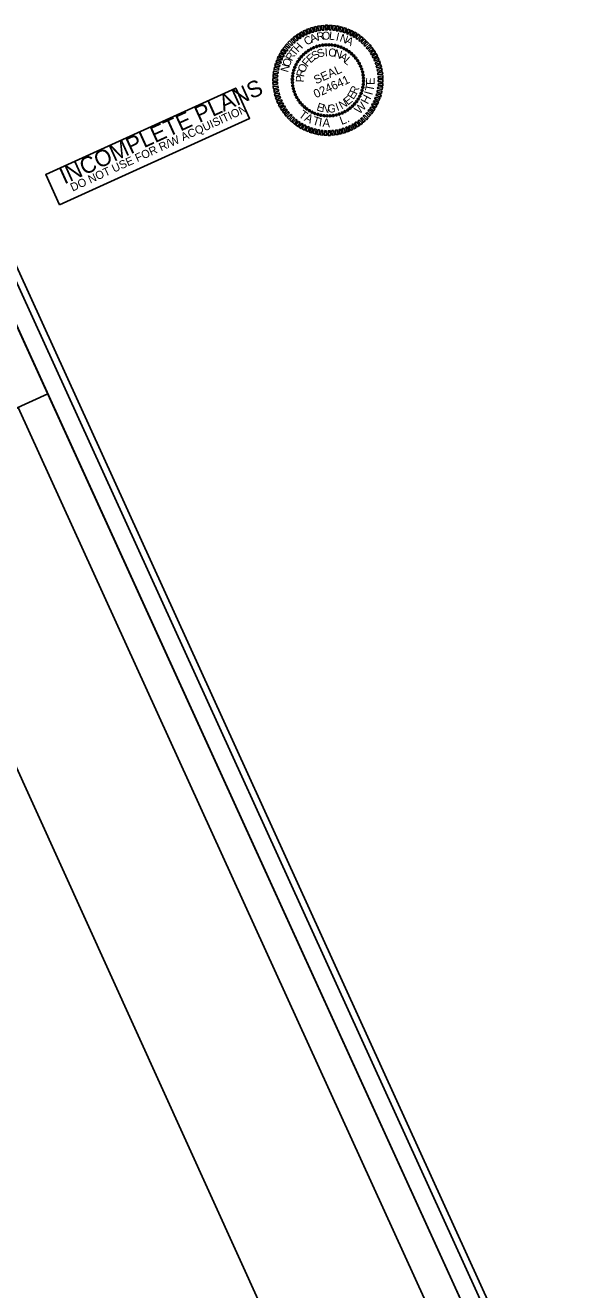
# Model space of a CAD drawing. Extents: x 2247910 to 2249896, y 662531 to 664266.
# Drawn here: x 2249507 to 2249896, y 663375 to 664266 of the extents above; entities that cross this region are included whole.
import ezdxf

# ---------------------------------------------------------------- set-up
doc = ezdxf.new("R2010")
doc.units = 0
for name, color, linetype in [('Sheet Clip Boundary CELL', 7, 'Continuous'), ('Sheet Layout Plan Border', 7, 'Continuous'), ('Sheet Plan CELL', 7, 'Continuous'), ('Sheet Plan Layout CELL', 7, 'Continuous'), ('Sheet Plot Border Inside CELL', 7, 'Continuous'), ('Sheet Plot Border Outside CELL', 7, 'Continuous'), ('Sheet Professional Seal CELL', 7, 'Continuous'), ('Sheet Sticker Incomplete CELL', 7, 'Continuous')]:
    doc.layers.add(name, color=color, linetype=linetype)

msp = doc.modelspace()

# ---------------------------------------------------------------- linework, layer by layer
at = {"layer": 'Sheet Clip Boundary CELL'}
msp.add_lwpolyline([(2248241.67, 663371.06), (2248489.82, 662824.78), (2248551.22, 662641.58), (2248585.88, 662667.26), (2249638.09, 663136.85), (2249825.2, 663222.11), (2249759.42, 663344.83), (2249697.59, 663317.15), (2249673.42, 663362.44), (2249425.27, 663908.72), (2249477.5, 663985.14), (2249333.25, 663919.41), (2249245.56, 664111.86), (2248806.18, 663911.31), (2248826.45, 663856.95), (2248820.45, 663848.41), (2248540.82, 663728.18), (2248517.28, 663777.91), (2248115.83, 663597.06)], close=True, dxfattribs=at)
at = {"layer": 'Sheet Layout Plan Border'}
msp.add_lwpolyline([(2248198.13, 663481.51), (2248575.77, 662652.77), (2249849.75, 663233.3), (2249502.05, 663996.33), (2249329.83, 663917.85), (2249242.13, 664110.3), (2248140.38, 663608.25)], close=True, dxfattribs=at)
at = {"layer": 'Sheet Plan CELL'}
for points in [[(2249435.32, 664198.33), (2248070.33, 663576.33), (2248505.72, 662620.85), (2249870.7, 663242.85)], [(2248505.72, 662620.85), (2248070.31, 663576.29), (2249253.26, 664115.38), (2249268.84, 664081.19), (2249359.88, 664122.68), (2249406.53, 664020.29), (2249497.53, 664061.77), (2249870.7, 663242.85)]]:
    msp.add_lwpolyline(points, close=True, dxfattribs=at)
at = {"layer": 'Sheet Plan Layout CELL'}
for points in [[(2249305.27, 663906.66), (2249523.01, 664005.88), (2249435.34, 664198.34), (2249217.58, 664099.11)], [(2248070.31, 663576.29), (2248505.72, 662620.85), (2249870.68, 663242.84), (2249522.99, 664005.87), (2249305.27, 663906.66), (2249217.58, 664099.11)]]:
    msp.add_lwpolyline(points, close=True, dxfattribs=at)
at = {"layer": 'Sheet Plot Border Inside CELL'}
msp.add_lwpolyline([(2248367.09, 662554.92), (2249883.1, 663245.75), (2249445.65, 664205.77), (2247929.62, 663514.94)], close=True, dxfattribs=at)
at = {"layer": 'Sheet Plot Border Outside CELL'}
msp.add_lwpolyline([(2248363.56, 662531.33), (2249895.5, 663229.41), (2249441.45, 664225.83), (2247909.5, 663527.75)], close=True, dxfattribs=at)
at = {"layer": 'Sheet Professional Seal CELL'}
for p, q in [((2249701.49, 664243.45), (2249701.49, 664243.45)), ((2249702.98, 664245), (2249702.98, 664245)), ((2249704.64, 664246.42), (2249704.64, 664246.42)), ((2249706.47, 664247.7), (2249706.47, 664247.7)), ((2249708.31, 664248.86), (2249708.31, 664248.86)), ((2249710.29, 664249.82), (2249710.29, 664249.82)), ((2249712.35, 664250.6), (2249712.35, 664250.6)), ((2249714.45, 664251.17), (2249714.45, 664251.17)), ((2249716.55, 664251.63), (2249716.55, 664251.63)), ((2249718.75, 664251.87), (2249718.75, 664251.87)), ((2249720.94, 664251.88), (2249720.94, 664251.88)), ((2249723.13, 664251.78), (2249723.13, 664251.78)), ((2249725.29, 664251.39), (2249725.29, 664251.39)), ((2249727.44, 664250.88), (2249727.44, 664250.88)), ((2249729.47, 664250.16), (2249729.47, 664250.16)), ((2249731.52, 664249.28), (2249731.52, 664249.28)), ((2249733.39, 664248.21), (2249733.39, 664248.21)), ((2249735.22, 664246.96), (2249735.22, 664246.96)), ((2249736.94, 664245.6), (2249736.94, 664245.6)), ((2249738.5, 664244.11), (2249738.5, 664244.11)), ((2249696.92, 664235.98), (2249696.92, 664235.98)), ((2249697.8, 664238.03), (2249697.8, 664238.03)), ((2249698.88, 664239.89), (2249698.88, 664239.89)), ((2249700.13, 664241.73), (2249700.13, 664241.73)), ((2249739.92, 664242.45), (2249739.92, 664242.45)), ((2249741.19, 664240.61), (2249741.19, 664240.61)), ((2249742.36, 664238.78), (2249742.36, 664238.78)), ((2249743.31, 664236.8), (2249743.31, 664236.8)), ((2249744.09, 664234.74), (2249744.09, 664234.74)), ((2249695.21, 664227.45), (2249695.21, 664227.45)), ((2249695.22, 664225.26), (2249695.22, 664225.26)), ((2249695.31, 664229.64), (2249695.31, 664229.64)), ((2249695.7, 664231.79), (2249695.7, 664231.79)), ((2249696.2, 664233.95), (2249696.2, 664233.95)), ((2249720.29, 664226.8), (2249720.29, 664226.8)), ((2249744.66, 664232.63), (2249744.66, 664232.63)), ((2249745.13, 664230.54), (2249745.13, 664230.54)), ((2249745.36, 664228.34), (2249745.36, 664228.34)), ((2249745.37, 664226.14), (2249745.37, 664226.14)), ((2249695.45, 664223.05), (2249695.45, 664223.05)), ((2249695.92, 664220.96), (2249695.92, 664220.96)), ((2249696.49, 664218.86), (2249696.49, 664218.86)), ((2249697.27, 664216.79), (2249697.27, 664216.79)), ((2249743.66, 664217.61), (2249743.66, 664217.61)), ((2249744.38, 664219.64), (2249744.38, 664219.64)), ((2249744.88, 664221.8), (2249744.88, 664221.8)), ((2249745.27, 664223.95), (2249745.27, 664223.95)), ((2249698.22, 664214.81), (2249698.22, 664214.81)), ((2249699.39, 664212.98), (2249699.39, 664212.98)), ((2249700.67, 664211.14), (2249700.67, 664211.14)), ((2249702.08, 664209.48), (2249702.08, 664209.48)), ((2249703.64, 664207.99), (2249703.64, 664207.99)), ((2249737.6, 664208.59), (2249737.6, 664208.59)), ((2249739.09, 664210.15), (2249739.09, 664210.15)), ((2249740.45, 664211.86), (2249740.45, 664211.86)), ((2249741.7, 664213.7), (2249741.7, 664213.7)), ((2249742.78, 664215.56), (2249742.78, 664215.56)), ((2249705.36, 664206.63), (2249705.36, 664206.63)), ((2249707.19, 664205.38), (2249707.19, 664205.38)), ((2249709.06, 664204.31), (2249709.06, 664204.31)), ((2249711.11, 664203.43), (2249711.11, 664203.43)), ((2249713.14, 664202.71), (2249713.14, 664202.71)), ((2249715.29, 664202.21), (2249715.29, 664202.21)), ((2249717.45, 664201.81), (2249717.45, 664201.81)), ((2249719.64, 664201.71), (2249719.64, 664201.71)), ((2249721.83, 664201.72), (2249721.83, 664201.72)), ((2249724.03, 664201.96), (2249724.03, 664201.96)), ((2249726.13, 664202.42), (2249726.13, 664202.42)), ((2249728.23, 664202.99), (2249728.23, 664202.99)), ((2249730.29, 664203.77), (2249730.29, 664203.77)), ((2249732.28, 664204.73), (2249732.28, 664204.73)), ((2249734.11, 664205.89), (2249734.11, 664205.89)), ((2249735.94, 664207.17), (2249735.94, 664207.17))]:
    msp.add_line(p, q, dxfattribs=at)
for points in [[(2249702.28, 664257.38), (2249700.45, 664260.06), (2249701.91, 664260.95), (2249703.31, 664258.01)], [(2249704.45, 664258.64), (2249702.87, 664261.5), (2249704.4, 664262.14), (2249705.56, 664259.1)], [(2249706.65, 664259.59), (2249705.31, 664262.55), (2249706.83, 664263.19), (2249707.77, 664260.05)], [(2249708.99, 664260.49), (2249707.82, 664263.53), (2249709.45, 664263.95), (2249710.17, 664260.81)], [(2249711.34, 664261.13), (2249710.42, 664264.22), (2249712.03, 664264.68), (2249712.49, 664261.49)], [(2249713.89, 664261.68), (2249713, 664264.85), (2249714.71, 664265.19), (2249714.95, 664261.89)], [(2249716.34, 664262.09), (2249715.74, 664265.22), (2249717.36, 664265.41), (2249717.44, 664262.21)], [(2249718.76, 664262.2), (2249718.5, 664265.55), (2249720.02, 664265.58), (2249719.95, 664262.36)], [(2249721.2, 664262.27), (2249721.12, 664265.47), (2249722.82, 664265.48), (2249722.43, 664262.23)], [(2249723.77, 664262.18), (2249723.82, 664265.33), (2249725.54, 664265.18), (2249724.89, 664262.03)], [(2249726.11, 664261.76), (2249726.5, 664265.13), (2249728.12, 664264.71), (2249727.36, 664261.67)], [(2249728.6, 664261.25), (2249729.14, 664264.52), (2249730.78, 664264.05), (2249729.75, 664261)], [(2249730.97, 664260.62), (2249731.75, 664263.84), (2249733.34, 664263.25), (2249732.14, 664260.34)], [(2249733.33, 664259.78), (2249734.31, 664262.81), (2249735.9, 664262.21), (2249734.35, 664259.36)], [(2249735.67, 664258.87), (2249736.83, 664261.87), (2249738.35, 664261.08), (2249736.72, 664258.25)], [(2249692.89, 664249.41), (2249690.27, 664251.3), (2249691.39, 664252.58), (2249693.7, 664250.28)], [(2249694.45, 664251.28), (2249692.07, 664253.38), (2249693.18, 664254.55), (2249695.47, 664252.07)], [(2249696.35, 664253.03), (2249694.06, 664255.28), (2249695.28, 664256.33), (2249697.16, 664253.78)], [(2249698.26, 664254.61), (2249696, 664257.04), (2249697.4, 664258.07), (2249699.12, 664255.28)], [(2249700.22, 664256.11), (2249698.16, 664258.69), (2249699.6, 664259.51), (2249701.25, 664256.74)], [(2249737.84, 664257.71), (2249739.2, 664260.64), (2249740.67, 664259.72), (2249738.78, 664257.1)], [(2249739.88, 664256.39), (2249741.5, 664259.22), (2249742.99, 664258.25), (2249740.93, 664255.77)], [(2249741.97, 664254.93), (2249743.79, 664257.68), (2249745.03, 664256.54), (2249742.91, 664254.31)], [(2249743.78, 664253.39), (2249745.84, 664255.97), (2249747.09, 664254.79), (2249744.69, 664252.59)], [(2249745.57, 664251.62), (2249747.8, 664254.07), (2249748.95, 664252.89), (2249746.46, 664250.87)], [(2249747.29, 664249.77), (2249749.73, 664252.14), (2249750.68, 664250.77), (2249748.05, 664248.96)], [(2249687.66, 664240.99), (2249684.75, 664242.08), (2249685.34, 664243.67), (2249688.24, 664242.02)], [(2249688.84, 664243.23), (2249685.89, 664244.52), (2249686.68, 664246.03), (2249689.43, 664244.21)], [(2249689.94, 664245.38), (2249687.2, 664246.93), (2249687.99, 664248.34), (2249690.7, 664246.38)], [(2249691.43, 664247.43), (2249688.62, 664249.12), (2249689.7, 664250.49), (2249692.04, 664248.37)], [(2249748.83, 664247.83), (2249751.31, 664250.01), (2249752.28, 664248.58), (2249749.54, 664247)], [(2249750.24, 664245.84), (2249752.91, 664247.82), (2249753.75, 664246.34), (2249750.92, 664244.83)], [(2249751.51, 664243.78), (2249754.3, 664245.49), (2249755.1, 664243.98), (2249752.1, 664242.73)], [(2249685.51, 664233.9), (2249682.34, 664234.33), (2249682.61, 664236.04), (2249685.7, 664235.04)], [(2249686.08, 664236.26), (2249682.91, 664236.95), (2249683.37, 664238.59), (2249686.35, 664237.36)], [(2249686.89, 664238.71), (2249683.72, 664239.52), (2249684.38, 664241.08), (2249687.28, 664239.77)], [(2249752.59, 664241.52), (2249755.49, 664243.01), (2249756.19, 664241.46), (2249753.09, 664240.43)], [(2249753.58, 664239.23), (2249756.58, 664240.49), (2249757.17, 664238.94), (2249753.99, 664238.1)], [(2249754.35, 664236.94), (2249757.39, 664238), (2249757.91, 664236.37), (2249754.62, 664235.75)], [(2249755.04, 664234.45), (2249758.03, 664235.38), (2249758.42, 664233.69), (2249755.12, 664233.33)], [(2249684.82, 664226.5), (2249681.52, 664226.26), (2249681.56, 664227.98), (2249684.81, 664227.71)], [(2249684.82, 664224.08), (2249681.62, 664223.62), (2249681.57, 664225.3), (2249684.88, 664225.27)], [(2249684.77, 664229.01), (2249681.66, 664228.96), (2249681.7, 664230.68), (2249684.92, 664230.12)], [(2249684.97, 664231.46), (2249681.8, 664231.67), (2249682.13, 664233.35), (2249685.33, 664232.61)], [(2249755.45, 664232), (2249758.54, 664232.7), (2249758.91, 664231.05), (2249755.52, 664230.88)], [(2249755.76, 664229.51), (2249758.96, 664229.97), (2249759.01, 664228.29), (2249755.7, 664228.32)], [(2249755.77, 664227.09), (2249759.06, 664227.33), (2249759.02, 664225.61), (2249755.77, 664225.88)], [(2249685.13, 664221.59), (2249682.04, 664220.89), (2249681.68, 664222.54), (2249685.06, 664222.71)], [(2249685.54, 664219.14), (2249682.55, 664218.21), (2249682.16, 664219.91), (2249685.46, 664220.26)], [(2249686.23, 664216.65), (2249683.19, 664215.59), (2249682.67, 664217.22), (2249685.96, 664217.85)], [(2249754.5, 664217.34), (2249757.67, 664216.64), (2249757.21, 664215), (2249754.23, 664216.23)], [(2249755.07, 664219.69), (2249758.24, 664219.26), (2249757.97, 664217.55), (2249754.88, 664218.55)], [(2249755.61, 664222.13), (2249758.78, 664221.93), (2249758.45, 664220.24), (2249755.26, 664220.98)], [(2249755.81, 664224.58), (2249758.92, 664224.63), (2249758.88, 664222.91), (2249755.66, 664223.47)], [(2249687, 664214.36), (2249684, 664213.1), (2249683.41, 664214.65), (2249686.59, 664215.5)], [(2249687.99, 664212.07), (2249685.1, 664210.58), (2249684.39, 664212.13), (2249687.49, 664213.16)], [(2249689.07, 664209.81), (2249686.28, 664208.1), (2249685.49, 664209.61), (2249688.48, 664210.86)], [(2249690.34, 664207.75), (2249687.67, 664205.77), (2249686.83, 664207.25), (2249689.66, 664208.76)], [(2249750.64, 664208.21), (2249753.38, 664206.66), (2249752.59, 664205.25), (2249749.88, 664207.21)], [(2249751.74, 664210.36), (2249754.69, 664209.07), (2249753.9, 664207.56), (2249751.15, 664209.38)], [(2249752.92, 664212.6), (2249755.83, 664211.51), (2249755.24, 664209.92), (2249752.35, 664211.57)], [(2249753.69, 664214.88), (2249756.87, 664214.07), (2249756.2, 664212.51), (2249753.3, 664213.82)], [(2249691.75, 664205.76), (2249689.27, 664203.59), (2249688.3, 664205.01), (2249691.04, 664206.59)], [(2249693.29, 664203.82), (2249690.85, 664201.45), (2249689.9, 664202.82), (2249692.53, 664204.63)], [(2249695.01, 664201.97), (2249692.78, 664199.52), (2249691.63, 664200.7), (2249694.12, 664202.72)], [(2249696.81, 664200.21), (2249694.74, 664197.62), (2249693.49, 664198.8), (2249695.89, 664201)], [(2249698.61, 664198.66), (2249696.79, 664195.91), (2249695.55, 664197.05), (2249697.67, 664199.28)], [(2249742.32, 664198.98), (2249744.58, 664196.55), (2249743.18, 664195.52), (2249741.47, 664198.31)], [(2249744.23, 664200.56), (2249746.52, 664198.31), (2249745.3, 664197.26), (2249743.42, 664199.81)], [(2249746.13, 664202.31), (2249748.51, 664200.21), (2249747.4, 664199.04), (2249745.12, 664201.52)], [(2249747.69, 664204.18), (2249750.31, 664202.29), (2249749.19, 664201.01), (2249746.88, 664203.31)], [(2249749.15, 664206.16), (2249751.96, 664204.47), (2249750.88, 664203.1), (2249748.54, 664205.22)], [(2249700.7, 664197.2), (2249699.08, 664194.37), (2249697.59, 664195.34), (2249699.65, 664197.82)], [(2249702.74, 664195.88), (2249701.38, 664192.95), (2249699.91, 664193.87), (2249701.8, 664196.49)], [(2249704.91, 664194.72), (2249703.75, 664191.72), (2249702.24, 664192.52), (2249703.86, 664195.34)], [(2249707.25, 664193.81), (2249706.27, 664190.78), (2249704.68, 664191.38), (2249706.24, 664194.23)], [(2249709.61, 664192.97), (2249708.83, 664189.75), (2249707.24, 664190.34), (2249708.44, 664193.25)], [(2249711.99, 664192.34), (2249711.44, 664189.07), (2249709.8, 664189.54), (2249710.83, 664192.59)], [(2249714.47, 664191.83), (2249714.08, 664188.47), (2249712.47, 664188.88), (2249713.22, 664191.92)], [(2249716.81, 664191.41), (2249716.76, 664188.26), (2249715.04, 664188.41), (2249715.69, 664191.56)], [(2249719.38, 664191.32), (2249719.46, 664188.12), (2249717.76, 664188.11), (2249718.15, 664191.36)], [(2249721.82, 664191.39), (2249722.08, 664188.04), (2249720.56, 664188.01), (2249720.63, 664191.23)], [(2249724.24, 664191.5), (2249724.84, 664188.37), (2249723.22, 664188.18), (2249723.14, 664191.39)], [(2249726.69, 664191.91), (2249727.59, 664188.74), (2249725.87, 664188.4), (2249725.63, 664191.7)], [(2249729.24, 664192.46), (2249730.16, 664189.37), (2249728.55, 664188.91), (2249728.09, 664192.1)], [(2249731.59, 664193.1), (2249732.76, 664190.06), (2249731.13, 664189.64), (2249730.42, 664192.78)], [(2249733.93, 664194), (2249735.28, 664191.04), (2249733.75, 664190.4), (2249732.81, 664193.54)], [(2249736.13, 664194.95), (2249737.71, 664192.09), (2249736.19, 664191.45), (2249735.02, 664194.49)], [(2249738.3, 664196.21), (2249740.13, 664193.53), (2249738.67, 664192.64), (2249737.27, 664195.58)], [(2249740.36, 664197.48), (2249742.42, 664194.9), (2249740.98, 664194.08), (2249739.33, 664196.85)]]:
    msp.add_lwpolyline(points, close=True, dxfattribs=at)
for centre, major_axis in [((2249714.43, 664251.18), (-0.168, 0.7)), ((2249716.58, 664251.6), (-0.107, 0.712)), ((2249718.75, 664251.83), (-0.044, 0.719)), ((2249720.94, 664251.87), (0.019, 0.72)), ((2249723.12, 664251.71), (0.081, 0.715)), ((2249725.29, 664251.37), (0.143, 0.706)), ((2249701.5, 664243.41), (-0.539, 0.477)), ((2249703.02, 664244.98), (-0.496, 0.522)), ((2249704.67, 664246.42), (-0.448, 0.563)), ((2249706.44, 664247.71), (-0.398, 0.6)), ((2249708.32, 664248.83), (-0.344, 0.633)), ((2249710.28, 664249.79), (-0.287, 0.66)), ((2249712.33, 664250.58), (-0.229, 0.683)), ((2249727.41, 664250.84), (0.204, 0.69)), ((2249729.48, 664250.13), (0.264, 0.67)), ((2249731.48, 664249.24), (0.321, 0.644)), ((2249733.39, 664248.18), (0.376, 0.614)), ((2249735.2, 664246.96), (0.428, 0.579)), ((2249736.9, 664245.58), (0.477, 0.539)), ((2249738.48, 664244.06), (0.522, 0.496)), ((2249739.91, 664242.41), (0.563, 0.448)), ((2249696.24, 664233.91), (-0.69, 0.204)), ((2249696.95, 664235.98), (-0.67, 0.264)), ((2249697.84, 664237.98), (-0.644, 0.321)), ((2249698.9, 664239.9), (-0.614, 0.376)), ((2249700.13, 664241.71), (-0.579, 0.428)), ((2249741.2, 664240.64), (0.6, 0.398)), ((2249742.33, 664238.77), (0.633, 0.344)), ((2249743.29, 664236.8), (0.66, 0.287)), ((2249744.07, 664234.76), (0.683, 0.229)), ((2249695.22, 664227.45), (-0.72, 0.019)), ((2249695.26, 664225.26), (-0.719, -0.044)), ((2249695.37, 664229.63), (-0.715, 0.081)), ((2249695.71, 664231.79), (-0.706, 0.143)), ((2249744.68, 664232.66), (0.7, 0.168)), ((2249745.09, 664230.51), (0.712, 0.107)), ((2249745.32, 664228.33), (0.719, 0.044)), ((2249745.36, 664226.14), (0.72, -0.019)), ((2249695.49, 664223.08), (-0.712, -0.107)), ((2249695.9, 664220.94), (-0.7, -0.168)), ((2249696.51, 664218.83), (-0.683, -0.229)), ((2249697.29, 664216.79), (-0.66, -0.287)), ((2249742.74, 664215.61), (0.644, -0.321)), ((2249743.63, 664217.61), (0.67, -0.264)), ((2249744.34, 664219.68), (0.69, -0.204)), ((2249744.87, 664221.8), (0.706, -0.143)), ((2249745.21, 664223.96), (0.715, -0.081)), ((2249698.25, 664214.82), (-0.633, -0.344)), ((2249699.38, 664212.95), (-0.6, -0.398)), ((2249700.67, 664211.18), (-0.563, -0.448)), ((2249702.1, 664209.53), (-0.522, -0.496)), ((2249703.68, 664208.01), (-0.477, -0.539)), ((2249705.38, 664206.63), (-0.428, -0.579)), ((2249735.91, 664207.17), (0.448, -0.563)), ((2249737.56, 664208.61), (0.496, -0.522)), ((2249739.08, 664210.18), (0.539, -0.477)), ((2249740.45, 664211.88), (0.579, -0.428)), ((2249741.68, 664213.7), (0.614, -0.376)), ((2249707.19, 664205.41), (-0.376, -0.614)), ((2249709.1, 664204.35), (-0.321, -0.644)), ((2249711.1, 664203.46), (-0.264, -0.67)), ((2249713.17, 664202.75), (-0.204, -0.69)), ((2249715.3, 664202.22), (-0.143, -0.706)), ((2249717.46, 664201.88), (-0.081, -0.715)), ((2249719.64, 664201.72), (-0.019, -0.72)), ((2249721.83, 664201.76), (0.044, -0.719)), ((2249724, 664201.99), (0.107, -0.712)), ((2249726.15, 664202.41), (0.168, -0.7)), ((2249728.25, 664203.01), (0.229, -0.683)), ((2249730.3, 664203.8), (0.287, -0.66)), ((2249732.26, 664204.76), (0.344, -0.633)), ((2249734.14, 664205.88), (0.398, -0.6))]:
    msp.add_ellipse(centre, major_axis=major_axis, ratio=0.999708, dxfattribs=at)
at = {"layer": 'Sheet Sticker Incomplete CELL'}
msp.add_lwpolyline([(2249531.33, 664138.99), (2249521.59, 664160.37), (2249655.35, 664221.33), (2249665.1, 664199.94)], close=True, dxfattribs=at)

# ---------------------------------------------------------------- texts
at = {"layer": 'Sheet Professional Seal CELL'}
for s, height, rotation, p in [('O', 5.64, 1.93343, (2249716.12, 664255.34)), ('L', 5.64, 354.73314, (2249720.89, 664255.48)), ('H', 5.64, 45.13174, (2249699.3, 664246.19)), ('C', 5.64, 30.73213, (2249705.39, 664251.16)), ('A', 5.64, 23.53258, (2249708.86, 664253.07)), ('R', 5.64, 9.13336, (2249712.76, 664254.63)), ('I', 5.64, 347.5324, (2249725.57, 664254.98)), ('N', 5.64, 340.33117, (2249728.17, 664254.46)), ('A', 5.64, 333.12941, (2249732.08, 664253)), ('R', 5.64, 59.53277, (2249694.85, 664239.92)), ('T', 5.64, 52.33203, (2249697.03, 664243.34)), ('E', 5.64, 41.12333, (2249708.05, 664238.58)), ('S', 5.64, 31.76787, (2249710.75, 664240.96)), ('S', 5.64, 22.41266, (2249714.01, 664242.5)), ('I', 5.64, 3.70186, (2249718.21, 664243.65)), ('O', 5.64, 354.34574, (2249720.32, 664243.84)), ('N', 5.64, 344.98887, (2249724.2, 664243.41)), ('A', 5.64, 326.27253, (2249727.87, 664242.23)), ('L', 5.64, 316.91311, (2249731.08, 664239.9)), ('N', 5.64, 73.93576, (2249692.11, 664232.08)), ('O', 5.64, 66.734, (2249693, 664235.67)), ('R', 5.64, 78.55191, (2249703.4, 664228.88)), ('O', 5.64, 69.1935, (2249703.98, 664231.83)), ('F', 5.64, 50.47929, (2249705.76, 664235.89)), ('SEAL', 5.998, 24.51226, (2249711.93, 664223.92)), ('P', 5.64, 87.91115, (2249703.28, 664225.3)), ('024641', 5.998, 24.51226, (2249711.81, 664214.13)), ('E', 6, 87.63115, (2249753.07, 664223.44)), ('E', 5.64, 57.63635, (2249738.23, 664212.88)), ('R', 5.64, 66.99367, (2249740.48, 664216.5)), ('H', 6, 61.83328, (2249748.34, 664209.51)), ('I', 6, 74.34486, (2249751.42, 664215.99)), ('T', 6, 79.10933, (2249752.21, 664218.62)), ('E', 5.64, 342.78915, (2249711.86, 664205.75)), ('N', 5.64, 352.14622, (2249715.71, 664204.54)), ('G', 5.64, 1.5025, (2249720.1, 664204.07)), ('I', 5.64, 20.21346, (2249726.85, 664205.06)), ('N', 5.64, 29.56865, (2249729.96, 664206.31)), ('E', 5.64, 38.92402, (2249734.22, 664208.91)), ('W', 6, 46.12601, (2249742.61, 664202.56)), ('T', 6, 323.6774, (2249699.2, 664201.48)), ('A', 6, 332.19922, (2249703.18, 664198.63)), ('T', 6, 343.27759, (2249708.91, 664195.87)), ('I', 6, 351.79941, (2249713.62, 664194.53)), ('A', 6, 356.56388, (2249716.32, 664194.08)), ('L', 6, 20.42498, (2249729.89, 664195.27)), ('.', 6, 28.28829, (2249734.12, 664196.88))]:
    msp.add_text(s, height=height, rotation=rotation, dxfattribs=at).set_placement(p)
at = {"layer": 'Sheet Sticker Incomplete CELL'}
for s, height, p in [('INCOMPLETE PLANS', 11.52, (2249534.63, 664153.35)), ('DO NOT USE FOR R/W ACQUISITION', 5.76, (2249540.47, 664148.37))]:
    msp.add_text(s, height=height, rotation=24.49794, dxfattribs=at).set_placement(p)

doc.saveas('drawing.dxf')
